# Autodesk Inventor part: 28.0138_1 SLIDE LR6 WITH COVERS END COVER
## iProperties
Created: 2007-06
Part Number: 28.0138_1 SLIDE LR6 WITH COVERS END COVER
Document SubType Name: Modeling
Designer: Andy Moles
Material: ABS Plastic
Mass: 13.4307 g
Surface Area: 89.5925 cm^2
Volume: 12.6704 cm^3
Density: 1.06 g/cm^3
Author: Andy Moles
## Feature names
1. Base1
